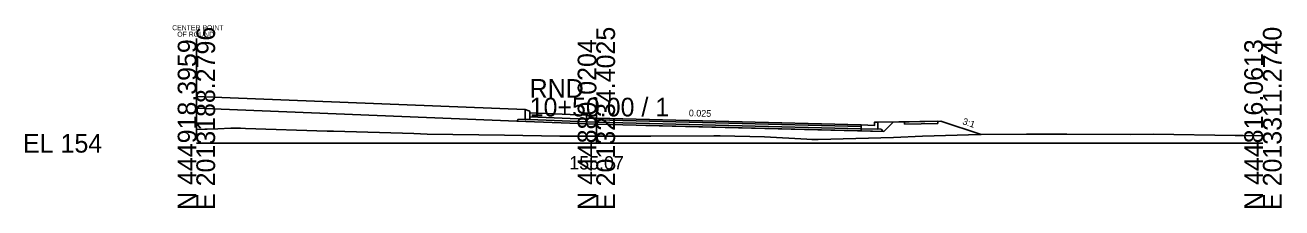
# Model space of a CAD drawing. Extents: x -26 to 163, y -10 to 7518.
# Drawn here: x -25.7 to 162.8, y 990.3 to 1017.7 of the extents above; entities that cross this region are included whole.
import ezdxf

# ---------------------------------------------------------------- set-up
doc = ezdxf.new("R2010")
doc.units = 0
for name, color, linetype in [('Exist Cross Section Cell', 7, 'Continuous'), ('Exist XS Center Line Elevation Label', 7, 'Continuous'), ('Exist XS Ground Line', 7, 'Continuous'), ('Prop CMT Conc Surface', 7, 'Continuous'), ('Prop CMT Concrete Structures', 7, 'Continuous'), ('Prop CMT Pvmt Course 1', 7, 'Continuous'), ('Prop CMT Pvmt Course 1 CG', 7, 'Continuous'), ('Prop CMT Pvmt Course 2', 7, 'Continuous'), ('Prop CMT Pvmt Course 3', 7, 'Continuous'), ('Prop CMT Pvmt Surface', 7, 'Continuous'), ('Prop CMT Shear Line', 7, 'Continuous'), ('Prop CMT Shear Line Text', 7, 'Continuous'), ('Prop CMT Slope Grass', 7, 'Continuous'), ('Prop CMT Subgrade Earthwork', 7, 'Continuous'), ('Prop XS Earthwork Shape', 7, 'Continuous'), ('Prop XS SE Text', 7, 'Continuous'), ('Prop XS Side Slope Text', 7, 'Continuous')]:
    doc.layers.add(name, color=color, linetype=linetype)

msp = doc.modelspace()

# ---------------------------------------------------------------- linework, layer by layer
at = {"layer": 'Exist Cross Section Cell'}
for p, q in [((60, 1000), (60, 1006.83)), ((0, 1000), (60, 1000)), ((60, 1000), (160, 1000))]:
    msp.add_line(p, q, dxfattribs=at)
at = {"layer": 'Exist XS Ground Line'}
msp.add_lwpolyline([(0, 1002.05), (1.26, 1002.11), (1.6, 1002.12), (3.22, 1002.19), (5.16, 1002.28), (5.7, 1002.27), (6.6, 1002.28), (7.38, 1002.24), (19.6, 1001.83), (20.59, 1001.82), (32.63, 1001.45), (33.62, 1001.41), (34.62, 1001.38), (46.24, 1001.2), (54.51, 1001.08), (60, 1001.07), (64.08, 1001.06), (68.18, 1001.06), (77.64, 1001.13), (78.14, 1001.13), (78.55, 1001.12), (85.24, 1000.96), (91.56, 1000.6), (92.34, 1000.55), (93.28, 1000.56), (104.57, 1000.89), (108.92, 1001.09), (117.58, 1001.32), (124.55, 1001.37), (130.59, 1001.39), (140.19, 1001.34), (143.6, 1001.36), (155.83, 1001.19), (156.25, 1001.17), (157.01, 1001.17), (160, 1001.13)], dxfattribs=at)
at = {"layer": 'Prop CMT Conc Surface'}
for points in [[(50, 1004.73), (49.96, 1004.84), (49.85, 1004.88), (49.34, 1005.07)], [(50, 1004.57), (50, 1004.73)], [(60, 1003.77), (59.25, 1003.79), (59.25, 1003.96), (58.5, 1004.21)], [(101.71, 1002.65), (101.71, 1003.15), (102.21, 1003.15)], [(106.21, 1003.23), (111.21, 1003.33)], [(99.72, 1002.78), (101.71, 1002.65)]]:
    msp.add_lwpolyline(points, dxfattribs=at)
at = {"layer": 'Prop CMT Concrete Structures'}
for points in [[(50, 1004.73), (49.96, 1004.84), (49.85, 1004.88), (49.34, 1005.07)], [(49.34, 1005.07), (49.34, 1003.57)], [(49.34, 1003.57), (50, 1003.57)], [(50, 1004.57), (50, 1004.73)], [(50, 1003.57), (50, 1004.57)], [(50, 1004.57), (50, 1003.98)], [(58.5, 1004.21), (50, 1004.55)], [(50, 1003.97), (58.5, 1003.62)], [(60, 1003.77), (59.25, 1003.79), (59.25, 1003.96), (58.5, 1004.21)], [(58.5, 1004.21), (58.5, 1003.23)], [(58.5, 1003.62), (58.5, 1004.21)], [(58.5, 1003.23), (60, 1003.19)], [(60, 1003.19), (60, 1003.77)], [(99.72, 1002.78), (101.71, 1002.65), (101.71, 1003.15), (102.21, 1003.15)], [(102.21, 1003.15), (102.21, 1002.13), (99.72, 1002.19)], [(111.21, 1003.33), (106.21, 1003.23)], [(106.21, 1003.23), (106.21, 1002.89)], [(111.21, 1002.99), (111.21, 1003.33)], [(99.72, 1002.19), (99.72, 1002.78)], [(106.21, 1002.89), (111.21, 1002.99)]]:
    msp.add_lwpolyline(points, dxfattribs=at)
at = {"layer": 'Prop CMT Pvmt Course 1'}
for points in [[(60, 1003.77), (99.72, 1002.78)], [(60, 1003.52), (60, 1003.77)], [(99.72, 1002.53), (60, 1003.52)], [(99.72, 1002.78), (99.72, 1002.53)]]:
    msp.add_lwpolyline(points, dxfattribs=at)
msp.add_lwpolyline([(60, 1003.52), (60, 1003.65), (60, 1003.65), (60, 1003.52)], close=True, dxfattribs=at)
at = {"layer": 'Prop CMT Pvmt Course 1 CG'}
for points in [[(60, 1002.86), (60, 1003.19)], [(99.72, 1002.19), (102.71, 1002.12), (103.05, 1001.78)], [(99.72, 1001.86), (99.72, 1002.19)], [(103.13, 1001.77), (99.72, 1001.86)]]:
    msp.add_lwpolyline(points, dxfattribs=at)
at = {"layer": 'Prop CMT Pvmt Course 2'}
for points in [[(60, 1003.19), (60, 1003.52)], [(60, 1003.52), (99.72, 1002.53)], [(99.72, 1002.19), (60, 1003.19)], [(99.72, 1002.53), (99.72, 1002.19)]]:
    msp.add_lwpolyline(points, dxfattribs=at)
at = {"layer": 'Prop CMT Pvmt Course 3'}
for points in [[(50, 1003.57), (58.5, 1003.23)], [(60, 1002.86), (60, 1003.19)], [(99.72, 1001.86), (60, 1002.86)], [(67.43, 1002.67), (103.13, 1001.77)], [(99.72, 1002.19), (99.72, 1001.86)]]:
    msp.add_lwpolyline(points, dxfattribs=at)
at = {"layer": 'Prop CMT Pvmt Surface'}
msp.add_lwpolyline([(60, 1003.77), (99.72, 1002.78)], dxfattribs=at)
at = {"layer": 'Prop CMT Shear Line'}
msp.add_line((0, 1000.71), (0, 1015.71), dxfattribs=at)
at = {"layer": 'Prop CMT Slope Grass'}
for p, q in [((49.34, 1005.05), (0, 1007.02)), ((48.06, 1003.33), (0, 1005.26))]:
    msp.add_line(p, q, dxfattribs=at)
msp.add_lwpolyline([(102.21, 1003.15), (111.68, 1003.34), (117.73, 1001.32)], dxfattribs=at)
at = {"layer": 'Prop CMT Subgrade Earthwork'}
for p, q in [((0, 1007.02), (0, 1002.05)), ((48.34, 1003.61), (48.06, 1003.33))]:
    msp.add_line(p, q, dxfattribs=at)
for points in [[(48.06, 1003.33), (60, 1002.86)], [(48.34, 1003.61), (49.34, 1003.57)], [(99.72, 1001.86), (103.13, 1001.77), (104.55, 1003.19)], [(60, 1002.86), (99.72, 1001.86)]]:
    msp.add_lwpolyline(points, dxfattribs=at)
at = {"layer": 'Prop XS Earthwork Shape'}
msp.add_lwpolyline([(48.06, 1003.33), (0, 1005.26), (0, 1002.05), (1.26, 1002.11), (1.6, 1002.12), (3.22, 1002.19), (5.16, 1002.28), (5.7, 1002.27), (6.6, 1002.28), (7.38, 1002.24), (19.6, 1001.83), (20.59, 1001.82), (32.63, 1001.45), (33.62, 1001.41), (34.62, 1001.38), (46.24, 1001.2), (54.51, 1001.08), (60, 1001.07), (64.08, 1001.06), (68.18, 1001.06), (77.64, 1001.13), (78.14, 1001.13), (78.55, 1001.12), (85.24, 1000.96), (91.56, 1000.6), (92.34, 1000.55), (93.28, 1000.56), (104.57, 1000.89), (108.92, 1001.09), (117.58, 1001.32), (117.73, 1001.32), (111.68, 1003.34), (104.55, 1003.19), (103.13, 1001.77), (99.72, 1001.86), (60, 1002.86)], close=True, dxfattribs=at)

# ---------------------------------------------------------------- texts
at = {"layer": 'Exist Cross Section Cell'}
for s, p in [('E 2013188.2796', (2.8, 990)), ('E 2013234.4025', (62.8, 990)), ('E 2013311.2740', (162.8, 990)), ('N 444918.3959', (0, 990)), ('N 444880.0204', (60, 990)), ('N 444816.0613', (160, 990))]:
    msp.add_text(s, height=2.8, rotation=90, dxfattribs=at).set_placement(p)
for s, p in [('RND', (50, 1006.83)), ('10+50.00 / 1', (50, 1004.03)), ('EL 154', (-26, 998.6))]:
    msp.add_text(s, height=2.8, dxfattribs=at).set_placement(p)
at = {"layer": 'Exist XS Center Line Elevation Label'}
msp.add_text('155.07', height=2, dxfattribs=at).set_placement((55.94, 996.07))
at = {"layer": 'Prop CMT Shear Line Text'}
for s, p in [('CENTER POINT', (-3.64, 1016.97)), ('OF ROUND', (-2.88, 1015.99))]:
    msp.add_text(s, height=0.75, dxfattribs=at).set_placement(p)
at = {"layer": 'Prop XS SE Text'}
msp.add_text('0.025', height=1, rotation=358.5613, dxfattribs=at).set_placement((73.87, 1004.05))
at = {"layer": 'Prop XS Side Slope Text'}
msp.add_text('3:1', height=1, rotation=341.5651, dxfattribs=at).set_placement((114.85, 1002.88))

doc.saveas('drawing.dxf')
